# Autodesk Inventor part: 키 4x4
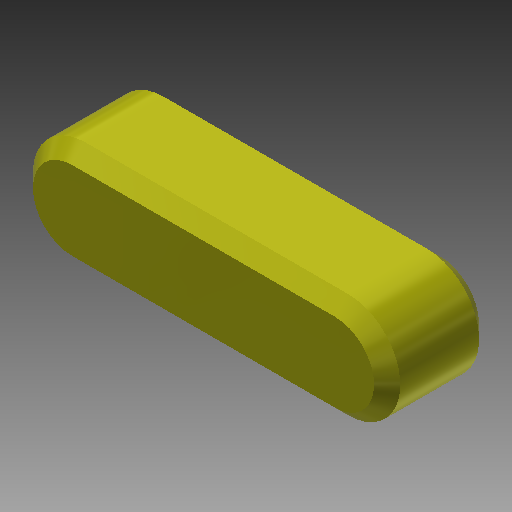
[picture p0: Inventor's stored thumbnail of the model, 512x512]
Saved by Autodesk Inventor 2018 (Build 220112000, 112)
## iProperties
Created: 2016-04
Part Number: 키 4x4
Document SubType Name: Modeling
Designer: mdu
Density: 7.86 g/cm^3
Mass: 1.65269 g
Surface Area: 2.35398 cm^2
Volume: 0.210265 cm^3
Material: 강철, 연강
Appearance: 노란색
Author: mdu
Revision Number: 1
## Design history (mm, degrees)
sketch "스케치1"
  geometry: L1 (-5, -2)-(5, -2); L2 (5, 2)-(-5, 2); A1 r 2 centre (5, 0) between (5, -2) and (5, 2); A2 r 2 centre (-5, 0) between (-5, 2) and (-5, -2); 2 further points
  constraints: 4 end point, 4 point on circle, 4 tangent, 2 centre point, 1 horizontal, 1 horizontal alignment, 1 midpoint, 1 parallel, 1 vertical alignment
  dimensions: "d0" = 4 distance between parallel lines of L1 L2; "d1" = 14 dimension on A1 A2
extrude "돌출1" new body sketch "스케치1" stored distance "d2" = 4; taper "d3" = 0 deg
chamfer "모따기1" distance "d4" = 0.5; stored, may be unused: second distance "d5" = 2, angle "d6" = 45 deg
node "솔리드1"
other parameters: "d0" = 4
